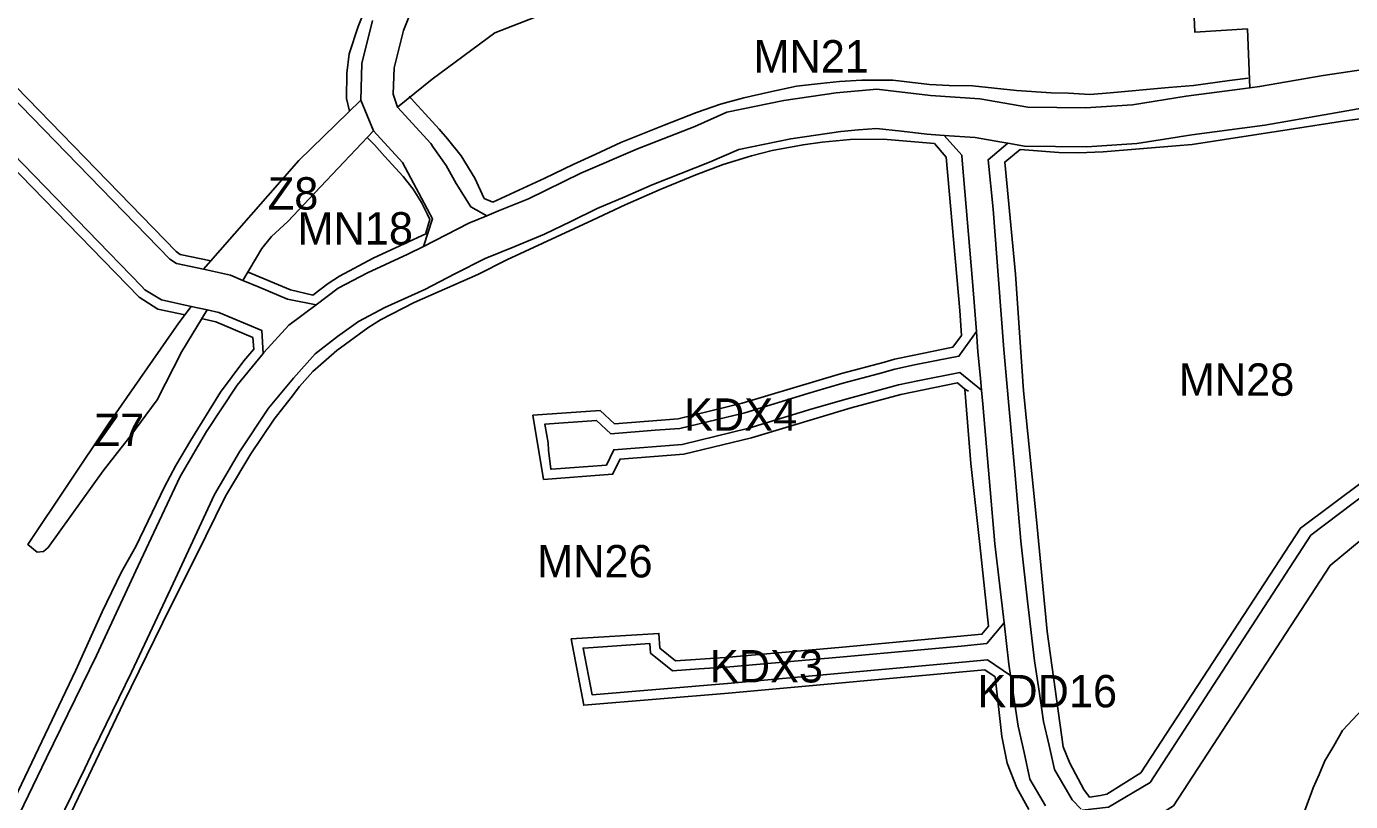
# Model space of a CAD drawing. Extents: x 7428841 to 7433518, y 5545054 to 5546840.
# Drawn here: x 7430252.9 to 7430661.7, y 5545310.2 to 5545549.4 of the extents above; entities that cross this region are included whole.
import ezdxf

# ---------------------------------------------------------------- set-up
doc = ezdxf.new("R2010")
doc.units = 0
for name, color, linetype in [('linie_rozgraniczajace', 7, 'Continuous'), ('linie_zabudowy_nieprzekraczalne', 7, 'Continuous'), ('oznaczenia_przeznaczen', 7, 'Continuous')]:
    doc.layers.add(name, color=color, linetype=linetype)

msp = doc.modelspace()

# ---------------------------------------------------------------- linework, layer by layer
at = {"layer": 'linie_rozgraniczajace'}
for points in [[(7430325.58, 5545455.53), (7430312.26, 5545461.16), (7430308.65, 5545461.94), (7430303.75, 5545463), (7430294.58, 5545464.99), (7430289.44, 5545468.09), (7430288.37, 5545469.23), (7430255.3, 5545503.38), (7430229.22, 5545530.19), (7430216.84, 5545543.13), (7430184.02, 5545578.55), (7430149.29, 5545617.28), (7430139.47, 5545621.59), (7430134.46, 5545628.43), (7430133.95, 5545633.65), (7430133.85, 5545634.69), (7430133.44, 5545638.87)], [(7430378.27, 5545570.82), (7430369.25, 5545548.19), (7430366.37, 5545536.66), (7430366.11, 5545528.5), (7430367.42, 5545524.57), (7430377.7, 5545513.34), (7430378.47, 5545512.13), (7430382.42, 5545506.51), (7430383.97, 5545503.73), (7430385.52, 5545500.95), (7430390.09, 5545493.72), (7430395.07, 5545490.98), (7430389.47, 5545488.67), (7430375.47, 5545481.53), (7430378.29, 5545490.08), (7430368.98, 5545507.48), (7430360.08, 5545517.18), (7430356.1, 5545526.65), (7430356.4, 5545538.02), (7430359.72, 5545551.27)], [(7430413.69, 5545553.71), (7430397.54, 5545547.49), (7430378.11, 5545533.14), (7430367.42, 5545524.57), (7430366.11, 5545528.5), (7430366.37, 5545536.66), (7430369.25, 5545548.19), (7430378.27, 5545570.82)], [(7430211.33, 5545566.73), (7430229.77, 5545546.84), (7430297.16, 5545477.57), (7430299.21, 5545476.27), (7430307.56, 5545474.46), (7430315.9, 5545472.65), (7430319.7, 5545471.04), (7430324.69, 5545468.93), (7430333.47, 5545465.22), (7430342.31, 5545463.53), (7430333.84, 5545457.18), (7430326.2, 5545448.73), (7430325.96, 5545448.44), (7430325.58, 5545455.53)], [(7430359.72, 5545551.27), (7430356.4, 5545538.02), (7430356.1, 5545526.65), (7430336.95, 5545508.06), (7430322.25, 5545491.26), (7430307.56, 5545474.46), (7430299.21, 5545476.27), (7430297.16, 5545477.57), (7430229.77, 5545546.84), (7430211.33, 5545566.73)], [(7430612.89, 5545563.81), (7430613.58, 5545547.7), (7430629.88, 5545548.67), (7430630.56, 5545530.48), (7430627.51, 5545530.08), (7430610.96, 5545527.88), (7430594.41, 5545525.28), (7430579.91, 5545524.28), (7430571.01, 5545524.39), (7430562.1, 5545524.5), (7430547.27, 5545527.06), (7430532.02, 5545528.13), (7430515.46, 5545530.04), (7430502.88, 5545528.94), (7430486.76, 5545526.58), (7430469.12, 5545522.94), (7430459.2, 5545518.59), (7430441.55, 5545511.62), (7430424.09, 5545504.14), (7430407.88, 5545496.26), (7430398.67, 5545492.47), (7430395.07, 5545490.98), (7430390.09, 5545493.72), (7430385.52, 5545500.95), (7430383.97, 5545503.73), (7430382.42, 5545506.51), (7430378.47, 5545512.13), (7430377.7, 5545513.34), (7430367.42, 5545524.57), (7430378.11, 5545533.14), (7430397.54, 5545547.49), (7430413.69, 5545553.71)], [(7430673.27, 5545537.3), (7430653.27, 5545534.31), (7430633.61, 5545530.89), (7430630.56, 5545530.48), (7430629.88, 5545548.67), (7430613.58, 5545547.7), (7430612.89, 5545563.81)], [(7430246.49, 5545297.57), (7430259.11, 5545323.6), (7430274.47, 5545355.22), (7430287.4, 5545382.87), (7430300.33, 5545410.51), (7430308.5, 5545424.44), (7430317.94, 5545438.72), (7430325.96, 5545448.44), (7430326.2, 5545448.73), (7430333.84, 5545457.18), (7430342.31, 5545463.53), (7430349.08, 5545468.61), (7430358.2, 5545473.42), (7430370.68, 5545479.09), (7430375.47, 5545481.53), (7430389.47, 5545488.67), (7430395.07, 5545490.98), (7430398.67, 5545492.47), (7430407.88, 5545496.26), (7430424.09, 5545504.14), (7430441.55, 5545511.62), (7430459.2, 5545518.59), (7430469.12, 5545522.94), (7430486.76, 5545526.58), (7430502.88, 5545528.94), (7430515.46, 5545530.04), (7430532.02, 5545528.13), (7430547.27, 5545527.06), (7430562.1, 5545524.5), (7430571.01, 5545524.39), (7430579.91, 5545524.28), (7430594.41, 5545525.28), (7430610.96, 5545527.88), (7430627.51, 5545530.08), (7430630.56, 5545530.48), (7430633.61, 5545530.89), (7430653.27, 5545534.31), (7430673.27, 5545537.3)], [(7430229.22, 5545530.19), (7430255.3, 5545503.38), (7430288.37, 5545469.23), (7430289.44, 5545468.09), (7430294.58, 5545464.99), (7430303.75, 5545463), (7430299.89, 5545457.9), (7430278.23, 5545426.76), (7430253.3, 5545389.54), (7430256.15, 5545387.15), (7430258.19, 5545387.31), (7430259.56, 5545388.61), (7430276.57, 5545412.22), (7430282.15, 5545419.31), (7430284.84, 5545422.74), (7430293.23, 5545434.19), (7430300.82, 5545449.08), (7430308.65, 5545461.94), (7430312.26, 5545461.16), (7430325.58, 5545455.53), (7430325.96, 5545448.44), (7430317.94, 5545438.72), (7430308.5, 5545424.44), (7430300.33, 5545410.51), (7430287.4, 5545382.87), (7430274.47, 5545355.22), (7430259.11, 5545323.6), (7430246.49, 5545297.57)], [(7430578.5, 5545307.83), (7430575.76, 5545310.63), (7430570.26, 5545320.02), (7430568.6, 5545327.46), (7430566.94, 5545334.9), (7430565.53, 5545344.23), (7430564.12, 5545353.57), (7430562, 5545372.03), (7430559.88, 5545390.5), (7430558.01, 5545412.01), (7430556.14, 5545433.51), (7430554.63, 5545449.67), (7430552.99, 5545471.36), (7430551.35, 5545493.05), (7430549.8, 5545508.27), (7430555.9, 5545513.39), (7430561, 5545512.51), (7430570.63, 5545512.4), (7430580.25, 5545512.28), (7430588, 5545512.81), (7430595.75, 5545513.34), (7430604.22, 5545514.67), (7430612.68, 5545516), (7430635.19, 5545519), (7430655.35, 5545522.49), (7430669.3, 5545524.96)], [(7430669.3, 5545524.96), (7430655.35, 5545522.49), (7430635.19, 5545519), (7430612.68, 5545516), (7430604.22, 5545514.67), (7430595.75, 5545513.34), (7430588, 5545512.81), (7430580.25, 5545512.28)], [(7430256.41, 5545290.6), (7430270.86, 5545320.33), (7430273.6, 5545325.96), (7430285.31, 5545350.06), (7430298.13, 5545377.49), (7430310.96, 5545404.92), (7430318.68, 5545418.09), (7430327.6, 5545431.58), (7430335.28, 5545440.88), (7430342.02, 5545448.33), (7430348.96, 5545453.68), (7430355.44, 5545458.39), (7430363.49, 5545462.64), (7430375.9, 5545468.28), (7430385.19, 5545473.02), (7430394.49, 5545477.76), (7430403.64, 5545481.53), (7430412.79, 5545485.31), (7430420.93, 5545489.27), (7430429.08, 5545493.23), (7430437.6, 5545496.87), (7430446.11, 5545500.52), (7430454.97, 5545504.02), (7430463.82, 5545507.51), (7430472.78, 5545511.45), (7430480.81, 5545513.1), (7430488.84, 5545514.75), (7430496.56, 5545515.88), (7430504.28, 5545517.01), (7430509.79, 5545517.5), (7430515.29, 5545517.98), (7430523.1, 5545517.08), (7430530.91, 5545516.18), (7430536.26, 5545515.81), (7430541.64, 5545509.72), (7430541.77, 5545508.17), (7430545.02, 5545470.67), (7430546.18, 5545455.24), (7430540.77, 5545447.64), (7430533.91, 5545446.29), (7430527.06, 5545444.95), (7430520.97, 5545443.6), (7430516.27, 5545442.29), (7430510.8, 5545440.83), (7430505.33, 5545439.37), (7430499.71, 5545437.75), (7430494.1, 5545436.13), (7430474.64, 5545430.19), (7430454.61, 5545425.35), (7430446.96, 5545424.83), (7430433.34, 5545423.69), (7430428.92, 5545427.83), (7430412.94, 5545426.67), (7430413.98, 5545420.89), (7430414.09, 5545418.58), (7430414.8, 5545412.76), (7430415.04, 5545412.78), (7430431.93, 5545414.04), (7430434.23, 5545418.75), (7430455.37, 5545420.39), (7430475.96, 5545425.37), (7430495.52, 5545431.34), (7430506.66, 5545434.55), (7430522.18, 5545438.75), (7430528.08, 5545440.06), (7430541.09, 5545442.61), (7430547.76, 5545437.15), (7430548.17, 5545432.8), (7430551.92, 5545389.7), (7430554.71, 5545365.36), (7430549.38, 5545358.92), (7430541.46, 5545358.11), (7430505.17, 5545354.85), (7430468.87, 5545351.59), (7430460.62, 5545351.07), (7430452.36, 5545350.55), (7430445.56, 5545355.95), (7430445.37, 5545358.9), (7430424.95, 5545357.54), (7430424.74, 5545357.53), (7430427.5, 5545343.11), (7430469.33, 5545346.61), (7430505.63, 5545349.87), (7430541.94, 5545353.14), (7430549.56, 5545353.92), (7430556.71, 5545349.04), (7430557.63, 5545342.97), (7430559.08, 5545333.43), (7430560.9, 5545325.25), (7430562.72, 5545317.06), (7430565.79, 5545311.83), (7430567.55, 5545308.83)], [(7430580.25, 5545512.28), (7430570.63, 5545512.4), (7430561, 5545512.51), (7430555.9, 5545513.39), (7430553.41, 5545513.82), (7430545.82, 5545515.14), (7430536.26, 5545515.81), (7430530.91, 5545516.18), (7430523.1, 5545517.08), (7430515.29, 5545517.98), (7430509.79, 5545517.5), (7430504.28, 5545517.01), (7430496.56, 5545515.88), (7430488.84, 5545514.75), (7430480.81, 5545513.1), (7430472.78, 5545511.45), (7430463.82, 5545507.51), (7430454.97, 5545504.02), (7430446.11, 5545500.52), (7430437.6, 5545496.87), (7430429.08, 5545493.23), (7430420.93, 5545489.27), (7430412.79, 5545485.31), (7430403.64, 5545481.53), (7430394.49, 5545477.76), (7430385.19, 5545473.02), (7430375.9, 5545468.28), (7430363.49, 5545462.64), (7430355.44, 5545458.39), (7430348.96, 5545453.68), (7430342.02, 5545448.33), (7430335.28, 5545440.88), (7430327.6, 5545431.58), (7430318.68, 5545418.09), (7430310.96, 5545404.92), (7430298.13, 5545377.49), (7430285.31, 5545350.06), (7430273.6, 5545325.96), (7430270.86, 5545320.33), (7430256.41, 5545290.6)], [(7430567.55, 5545308.83), (7430565.79, 5545311.83), (7430562.72, 5545317.06), (7430560.9, 5545325.25), (7430559.08, 5545333.43), (7430557.63, 5545342.97), (7430556.71, 5545349.04), (7430556.19, 5545352.52), (7430554.71, 5545365.36), (7430551.92, 5545389.7), (7430548.17, 5545432.8), (7430547.76, 5545437.15), (7430547.41, 5545440.9), (7430546.66, 5545449), (7430546.18, 5545455.24), (7430545.02, 5545470.67), (7430541.77, 5545508.17), (7430541.64, 5545509.72), (7430536.26, 5545515.81), (7430545.82, 5545515.14), (7430553.41, 5545513.82), (7430555.9, 5545513.39), (7430549.8, 5545508.27), (7430551.35, 5545493.05), (7430552.99, 5545471.36), (7430554.63, 5545449.67), (7430556.14, 5545433.51), (7430558.01, 5545412.01), (7430559.88, 5545390.5), (7430562, 5545372.03), (7430564.12, 5545353.57), (7430565.53, 5545344.23), (7430566.94, 5545334.9), (7430568.6, 5545327.46), (7430570.26, 5545320.02), (7430575.76, 5545310.63), (7430578.5, 5545307.83)], [(7430671.62, 5545396.42), (7430655.46, 5545383.04), (7430607.04, 5545308.84), (7430596.43, 5545302.16), (7430594.11, 5545298.72), (7430595.04, 5545291.17), (7430590.74, 5545295.75), (7430586.44, 5545300.33), (7430581.24, 5545305.02), (7430579.2, 5545307.11), (7430578.85, 5545307.47), (7430586.92, 5545308.36), (7430599.81, 5545316.06), (7430649.43, 5545392.37), (7430667.19, 5545405.74)], [(7430667.19, 5545405.74), (7430649.43, 5545392.37), (7430599.81, 5545316.06), (7430586.92, 5545308.36)], [(7430607.04, 5545308.84), (7430655.46, 5545383.04), (7430671.62, 5545396.42)], [(7430662.16, 5545217.46), (7430657.25, 5545233.5), (7430657.29, 5545236.72), (7430655.75, 5545260.21), (7430643.58, 5545259.98), (7430642.86, 5545267.43), (7430644.46, 5545280.38), (7430646.98, 5545305.71), (7430649.64, 5545312.97), (7430650.17, 5545314.36), (7430651.98, 5545318.53), (7430653.8, 5545322.71), (7430656.52, 5545327.37), (7430659.25, 5545332.04), (7430665.45, 5545338.74)], [(7430665.45, 5545338.74), (7430659.25, 5545332.04), (7430656.52, 5545327.37), (7430653.8, 5545322.71), (7430651.98, 5545318.53), (7430650.17, 5545314.36), (7430649.64, 5545312.97), (7430646.98, 5545305.71)]]:
    msp.add_lwpolyline(points, dxfattribs=at)
for points in [[(7430307.56, 5545474.46), (7430322.25, 5545491.26), (7430336.95, 5545508.06), (7430356.1, 5545526.65), (7430360.08, 5545517.18), (7430343.69, 5545499.91), (7430333.53, 5545489.2), (7430328.5, 5545484.57), (7430325.6, 5545480.89), (7430319.7, 5545471.04), (7430315.9, 5545472.65)], [(7430319.7, 5545471.04), (7430325.6, 5545480.89), (7430328.5, 5545484.57), (7430333.53, 5545489.2), (7430343.69, 5545499.91), (7430360.08, 5545517.18), (7430368.98, 5545507.48), (7430378.29, 5545490.08), (7430375.47, 5545481.53), (7430370.68, 5545479.09), (7430358.2, 5545473.42), (7430349.08, 5545468.61), (7430342.31, 5545463.53), (7430333.47, 5545465.22), (7430324.69, 5545468.93)], [(7430253.3, 5545389.54), (7430278.23, 5545426.76), (7430299.89, 5545457.9), (7430303.75, 5545463), (7430308.65, 5545461.94), (7430300.82, 5545449.08), (7430293.23, 5545434.19), (7430284.84, 5545422.74), (7430282.15, 5545419.31), (7430276.57, 5545412.22), (7430259.56, 5545388.61), (7430258.19, 5545387.31), (7430256.15, 5545387.15)], [(7430412.94, 5545426.67), (7430428.92, 5545427.83), (7430433.34, 5545423.69), (7430446.96, 5545424.83), (7430454.61, 5545425.35), (7430474.64, 5545430.19), (7430494.1, 5545436.13), (7430499.71, 5545437.75), (7430505.33, 5545439.37), (7430510.8, 5545440.83), (7430516.27, 5545442.29), (7430520.97, 5545443.6), (7430527.06, 5545444.95), (7430533.91, 5545446.29), (7430540.77, 5545447.64), (7430546.18, 5545455.24), (7430546.66, 5545449), (7430547.41, 5545440.9), (7430547.76, 5545437.15), (7430541.09, 5545442.61), (7430528.08, 5545440.06), (7430522.18, 5545438.75), (7430506.66, 5545434.55), (7430495.52, 5545431.34), (7430475.96, 5545425.37), (7430455.37, 5545420.39), (7430434.23, 5545418.75), (7430431.93, 5545414.04), (7430415.04, 5545412.78), (7430414.8, 5545412.76), (7430414.09, 5545418.58), (7430413.98, 5545420.89)], [(7430424.74, 5545357.53), (7430424.95, 5545357.54), (7430445.37, 5545358.9), (7430445.56, 5545355.95), (7430452.36, 5545350.55), (7430460.62, 5545351.07), (7430468.87, 5545351.59), (7430505.17, 5545354.85), (7430541.46, 5545358.11), (7430549.38, 5545358.92), (7430554.71, 5545365.36), (7430556.19, 5545352.52), (7430556.71, 5545349.04), (7430549.56, 5545353.92), (7430541.94, 5545353.14), (7430505.63, 5545349.87), (7430469.33, 5545346.61), (7430427.5, 5545343.11)]]:
    msp.add_lwpolyline(points, close=True, dxfattribs=at)
at = {"layer": 'linie_zabudowy_nieprzekraczalne'}
for points in [[(7430352.62, 5545523.31), (7430351.71, 5545527.21), (7430351.75, 5545535.04), (7430352.52, 5545541), (7430355.29, 5545549.4), (7430364.94, 5545573.76), (7430365.95, 5545577.43), (7430366.53, 5545582.28), (7430366.66, 5545589.17), (7430365.98, 5545593.7), (7430362.88, 5545602.83), (7430357.63, 5545614.99), (7430346.86, 5545634.84), (7430334.97, 5545656.8), (7430326.8, 5545671.95), (7430319.76, 5545684.81), (7430313.72, 5545695.75), (7430303.88, 5545701.34)], [(7430167.85, 5545631.23), (7430162.47, 5545626.69), (7430161.79, 5545625.86), (7430166.3, 5545621), (7430195.12, 5545588.64), (7430231.95, 5545548.9), (7430299.06, 5545479.91), (7430300.36, 5545479.08), (7430309.83, 5545477.03)], [(7430396.87, 5545495.16), (7430412.97, 5545502.64), (7430421.64, 5545506.77), (7430428.71, 5545510.01), (7430436.39, 5545513.63), (7430449.77, 5545518.92), (7430459.74, 5545522.9), (7430467.12, 5545525.46), (7430474.36, 5545527.41), (7430482.08, 5545529.12), (7430490.67, 5545530.98), (7430498.08, 5545531.8), (7430503.94, 5545532.47), (7430510.84, 5545532.88), (7430520.38, 5545532.82), (7430531.68, 5545531.52), (7430537.82, 5545531.25), (7430544.96, 5545531.08), (7430558.54, 5545529.63), (7430569.22, 5545528.95), (7430574.64, 5545528.82), (7430581.23, 5545528.39), (7430587.5, 5545528.96), (7430605.51, 5545530.55), (7430613.17, 5545531.25), (7430624.31, 5545532.75), (7430630.12, 5545533.48)], [(7430301.8, 5545460.36), (7430293.42, 5545462.17), (7430287.64, 5545465.84), (7430228.94, 5545526.18)], [(7430371, 5545527.88), (7430372.57, 5545526.21), (7430375.96, 5545522.45), (7430380.32, 5545517.69), (7430382.92, 5545514.77), (7430387.11, 5545509.48), (7430391.28, 5545502.57), (7430394.24, 5545496.35), (7430396.87, 5545495.16)], [(7430713.74, 5545525.55), (7430702.41, 5545524.91), (7430691.04, 5545524.2), (7430679.33, 5545522.67), (7430670.81, 5545521.77), (7430659.92, 5545520.25), (7430642.73, 5545517.62), (7430632.81, 5545516.12), (7430612.76, 5545513), (7430607.77, 5545512.58), (7430585.31, 5545510.76), (7430577.66, 5545510.42), (7430571.68, 5545510.52), (7430559.65, 5545511.42)], [(7430533.2, 5545513.33), (7430517.35, 5545514.63), (7430507.2, 5545514.54), (7430498.52, 5545513.76), (7430492.69, 5545512.92), (7430483.16, 5545511.19), (7430476.78, 5545509.53), (7430468, 5545506.85), (7430459.56, 5545503.65), (7430448.54, 5545499.06), (7430437.73, 5545494.35), (7430427.64, 5545489.6), (7430401.24, 5545477.38), (7430392.28, 5545472.89), (7430372.63, 5545464.2), (7430362.22, 5545458.89), (7430358.29, 5545456.43), (7430348.69, 5545449.44), (7430341.3, 5545442.92), (7430337.2, 5545438.31), (7430334.56, 5545434.86), (7430329.34, 5545428.19), (7430322.2, 5545417.52), (7430314.96, 5545405.41), (7430314.27, 5545404.25), (7430305.3, 5545385.96), (7430297.27, 5545370.02), (7430282.8, 5545340.62), (7430266.81, 5545306.93)], [(7430376.2, 5545485.6), (7430377.42, 5545489.79), (7430376.7, 5545491.38), (7430374.82, 5545495.12), (7430372.3, 5545499.2), (7430369.19, 5545503.11), (7430363.44, 5545509.44), (7430360.36, 5545512.91), (7430358.04, 5545515.14)], [(7430541.59, 5545454.06), (7430541.09, 5545461.76), (7430536.88, 5545509.09), (7430533.2, 5545513.33)], [(7430559.65, 5545511.42), (7430554.93, 5545507.55), (7430558.23, 5545472.94), (7430560.71, 5545436.94), (7430564.72, 5545397.16), (7430568.04, 5545362.67), (7430572.98, 5545327.08), (7430575.04, 5545321.98), (7430579.38, 5545313.91), (7430581.12, 5545311.48)], [(7430341.25, 5545466.49), (7430346.06, 5545470.06), (7430349.5, 5545472.37), (7430359.97, 5545477.89), (7430376.35, 5545485.49)], [(7430321.35, 5545473.6), (7430334.4, 5545468.08), (7430341.25, 5545466.49)], [(7430323.12, 5545449.81), (7430322.76, 5545453.46), (7430311.35, 5545458.29), (7430306.87, 5545459.26)], [(7430542.64, 5545437.49), (7430540.3, 5545439.38), (7430522.87, 5545435.83), (7430507.48, 5545431.67), (7430476.74, 5545422.47), (7430455.84, 5545417.42), (7430436.18, 5545415.89), (7430433.87, 5545411.17), (7430412.53, 5545409.59), (7430409.23, 5545429.4), (7430430.01, 5545430.92), (7430434.42, 5545426.78), (7430454.14, 5545428.32), (7430473.86, 5545433.09), (7430504.51, 5545442.26), (7430517.84, 5545445.84), (7430520.94, 5545446.68), (7430526.44, 5545447.89), (7430538.88, 5545450.41), (7430541.59, 5545454.06)], [(7430239.29, 5545297.24), (7430239.29, 5545297.24), (7430243.9, 5545299.69), (7430243.9, 5545299.69), (7430250.35, 5545313.39), (7430268.09, 5545350.71), (7430276.26, 5545368.76), (7430282.12, 5545380.85), (7430286.65, 5545388.92), (7430295.47, 5545407.3), (7430298.99, 5545413.85), (7430303.59, 5545421.71), (7430312.81, 5545436.57), (7430319.95, 5545446.16), (7430323.12, 5545449.81)], [(7430549.92, 5545364.25), (7430547.27, 5545389.53), (7430544.49, 5545414.52), (7430542.64, 5545437.49), (7430543.78, 5545436.8)], [(7430584.46, 5545312.01), (7430586.43, 5545312.41), (7430596.99, 5545319.05), (7430646.28, 5545394.58), (7430665.82, 5545409.14)], [(7430552.01, 5545348.62), (7430548.76, 5545350.83), (7430469.59, 5545343.62), (7430424.94, 5545339.88), (7430421.11, 5545360.33), (7430448.17, 5545362.06), (7430448.47, 5545357.47), (7430453.32, 5545353.62), (7430468.64, 5545354.58), (7430504.89, 5545357.84), (7430547.86, 5545361.8), (7430549.92, 5545364.25)], [(7430562.33, 5545307.67), (7430558.71, 5545314.33), (7430555.64, 5545321.98), (7430554.04, 5545330.27), (7430552.01, 5545348.62)], [(7430581.12, 5545311.48), (7430584.46, 5545312.01)]]:
    msp.add_lwpolyline(points, dxfattribs=at)

# ---------------------------------------------------------------- texts
at = {"layer": 'oznaczenia_przeznaczen'}
for s, p in [('MN21', (7430477.33, 5545535.21)), ('Z8', (7430327.39, 5545492.9)), ('MN18', (7430336.55, 5545482.1)), ('MN28', (7430608.65, 5545435.42)), ('KDX4', (7430455.93, 5545424.6)), ('Z7', (7430273.62, 5545419.91)), ('MN26', (7430410.54, 5545379.34)), ('KDX3', (7430463.89, 5545346.91)), ('KDD16', (7430546.51, 5545339.23))]:
    msp.add_text(s, height=10, dxfattribs=at).set_placement(p)

doc.saveas('drawing.dxf')
